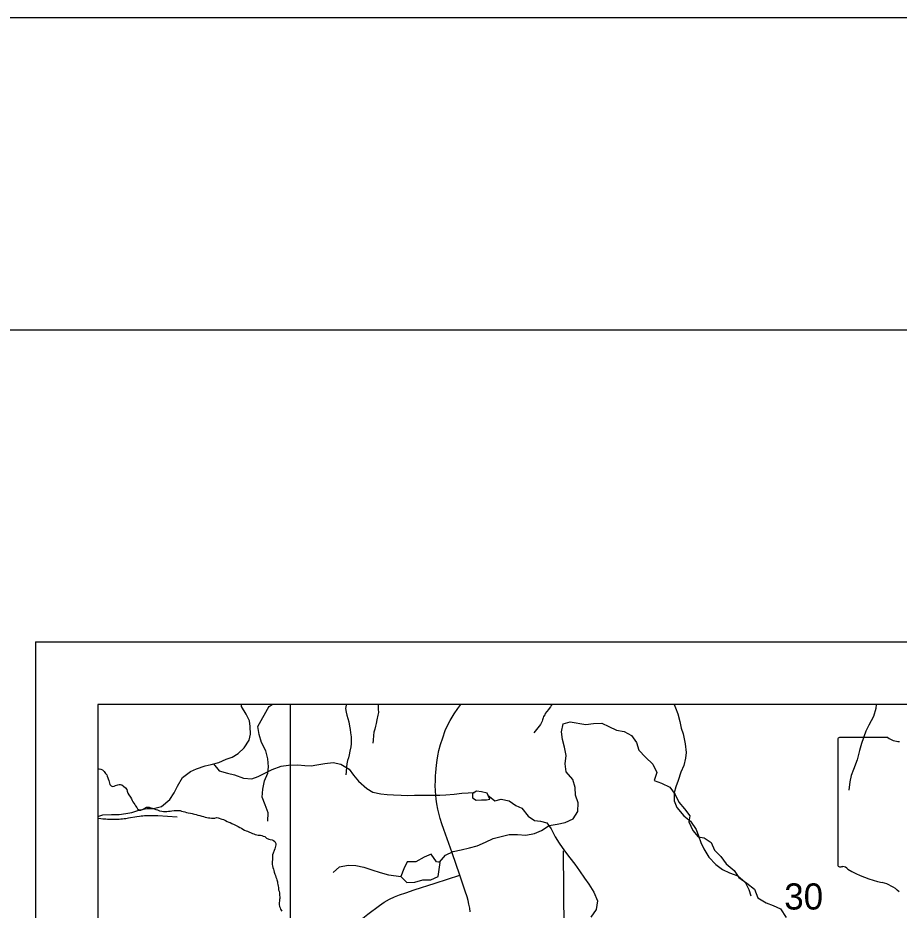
# Model space of a CAD drawing. Extents: x -21.1 to 50.3, y 0 to 22.1.
# Drawn here: x 1.972 to 3.383, y 20.57 to 22 of the extents above; entities that cross this region are included whole.
import ezdxf

# ---------------------------------------------------------------- set-up
doc = ezdxf.new("R2010")
doc.units = 0
for name, color, linetype in [('GM_X_County', 7, 'Continuous'), ('GM_X_County_Road', 7, 'Continuous'), ('GM_X_Minor_Lake', 7, 'Continuous'), ('GM_X_Minor_River', 7, 'Continuous'), ('GM_X_Section_Text', 7, 'Continuous'), ('GM_X_State_Route', 7, 'Continuous'), ('GM_X_State_Shield', 7, 'Continuous'), ('GM_X_Township_Road', 7, 'Continuous'), ('SH_Border', 7, 'Continuous'), ('SH_Cut_Line', 7, 'Continuous'), ('SH_Data', 7, 'Continuous')]:
    doc.layers.add(name, color=color, linetype=linetype)

msp = doc.modelspace()

# ---------------------------------------------------------------- linework, layer by layer
at = {"layer": 'GM_X_County'}
msp.add_lwpolyline([(8.9, 14.7464), (8.9, 20.9), (2.1, 20.9), (2.1, 14.1), (8.8932, 14.1)], dxfattribs=at)
at = {"layer": 'GM_X_County_Road'}
msp.add_lwpolyline([(2.4094, 20.2814), (2.4089, 20.3444), (2.4086, 20.5333), (2.4084, 20.714), (2.4086, 20.746), (2.4083, 20.9)], dxfattribs=at)
at = {"layer": 'GM_X_Minor_Lake'}
for points in [[(2.7234, 20.7578), (2.7144, 20.7601), (2.7064, 20.7608), (2.6999, 20.7574), (2.6999, 20.7502), (2.706, 20.7464), (2.7143, 20.7472), (2.7223, 20.7472), (2.7276, 20.7479)], [(2.7276, 20.7479), (2.7234, 20.7578)], [(2.648, 20.6469), (2.6422, 20.6475), (2.6338, 20.66), (2.6225, 20.6551), (2.6093, 20.6475), (2.5956, 20.6475), (2.59, 20.6365), (2.5854, 20.6244)], [(2.6473, 20.647), (2.6422, 20.6475), (2.6338, 20.66), (2.6225, 20.6551), (2.6093, 20.6475), (2.5956, 20.6475), (2.59, 20.6365), (2.5854, 20.6244)], [(2.5854, 20.6244), (2.5949, 20.6145), (2.6078, 20.6153), (2.6202, 20.6187), (2.6331, 20.6191), (2.6448, 20.6244), (2.648, 20.6469)], [(2.5854, 20.6244), (2.5949, 20.6145), (2.6078, 20.6153), (2.6202, 20.6187), (2.6331, 20.6191), (2.6448, 20.6244), (2.648, 20.6469)]]:
    msp.add_lwpolyline(points, dxfattribs=at)
at = {"layer": 'GM_X_Minor_River'}
msp.add_line((2.3741, 20.8968), (2.3791, 20.9), dxfattribs=at)
for points in [[(2.1669, 20.731), (2.1791, 20.7334), (2.189, 20.7331), (2.2018, 20.7365), (2.2151, 20.7478), (2.2219, 20.7585), (2.2273, 20.7691), (2.2356, 20.7827), (2.2481, 20.7926), (2.258, 20.7968), (2.272, 20.8013), (2.2815, 20.8036), (2.2936, 20.807), (2.3054, 20.812), (2.3148, 20.8154), (2.3247, 20.8214), (2.3342, 20.8302), (2.3425, 20.8427), (2.3444, 20.8525), (2.3441, 20.8643), (2.3426, 20.8738), (2.3376, 20.8844), (2.3301, 20.8965), (2.3301, 20.9)], [(2.3719, 20.7131), (2.3728, 20.7261), (2.3677, 20.7393), (2.3633, 20.7513), (2.3642, 20.7642), (2.3666, 20.7776), (2.3724, 20.7898), (2.373, 20.8001), (2.372, 20.813), (2.3688, 20.8258), (2.3618, 20.839), (2.3581, 20.8518), (2.3564, 20.8647), (2.3741, 20.8974)], [(2.4977, 20.9), (2.4974, 20.8989), (2.4966, 20.8936), (2.4974, 20.8875), (2.4986, 20.8826), (2.5002, 20.8773), (2.5021, 20.872), (2.503, 20.8651), (2.5038, 20.8595), (2.5046, 20.8545), (2.5054, 20.8481), (2.5058, 20.842), (2.5059, 20.8367), (2.5051, 20.8321), (2.5037, 20.8248), (2.5026, 20.8191), (2.5015, 20.8146), (2.5, 20.81), (2.4985, 20.805), (2.4982, 20.7997), (2.4975, 20.7921), (2.4972, 20.7871)], [(2.5485, 20.9), (2.5487, 20.8986), (2.5491, 20.8925), (2.5492, 20.8872), (2.5484, 20.8826), (2.547, 20.8754), (2.5459, 20.8696), (2.5448, 20.8651), (2.5433, 20.8605), (2.5418, 20.8555), (2.5415, 20.8502), (2.5408, 20.8426), (2.5404, 20.8377)], [(2.8273, 20.9), (2.8262, 20.8981), (2.8247, 20.8959), (2.8228, 20.8936), (2.8216, 20.8917), (2.8189, 20.8884), (2.8166, 20.8853), (2.8158, 20.8835), (2.8138, 20.8808), (2.813, 20.8785), (2.8122, 20.8751), (2.8114, 20.8732), (2.8099, 20.8698), (2.8087, 20.8676), (2.7981, 20.8545)], [(3.0232, 20.9), (3.0253, 20.8947), (3.029, 20.8849), (3.0321, 20.8727), (3.0343, 20.8621), (3.0377, 20.8526), (3.0408, 20.8367), (3.0423, 20.8231), (3.0411, 20.8136), (3.0385, 20.8022), (3.0339, 20.7912), (3.0294, 20.7783), (3.0256, 20.7681), (3.0229, 20.7582), (3.0233, 20.7453), (3.0271, 20.7347), (3.0384, 20.7214), (3.049, 20.7127), (3.0585, 20.6998), (3.0619, 20.6896), (3.0657, 20.6789), (3.0706, 20.6687), (3.0786, 20.6554), (3.0896, 20.6437), (3.1002, 20.6357), (3.1119, 20.63), (3.1248, 20.6255), (3.1366, 20.6152), (3.1426, 20.6035), (3.1456, 20.5932)], [(3.3466, 20.9), (3.3463, 20.8936), (3.3425, 20.8804), (3.3349, 20.8667), (3.33, 20.8572), (3.3232, 20.8375), (3.3201, 20.8261), (3.316, 20.8113), (3.3103, 20.7958), (3.3068, 20.7863), (3.3046, 20.7757), (3.303, 20.7628)], [(2.6473, 20.647), (2.657, 20.6582), (2.6693, 20.6641), (2.6818, 20.667), (2.6953, 20.6702), (2.7074, 20.6735), (2.7209, 20.679), (2.7329, 20.6849), (2.7457, 20.6882), (2.7589, 20.6915), (2.7721, 20.6913), (2.7854, 20.6904), (2.7993, 20.6929), (2.8106, 20.6981), (2.8226, 20.7059), (2.8354, 20.708), (2.8482, 20.7105), (2.861, 20.7164), (2.8687, 20.7283), (2.8692, 20.742), (2.8652, 20.7548), (2.8642, 20.7669), (2.8606, 20.7794), (2.8498, 20.7917), (2.8484, 20.805), (2.8501, 20.8179), (2.8472, 20.8315), (2.8444, 20.8436), (2.8426, 20.8561), (2.845, 20.8687), (2.8563, 20.8719), (2.8814, 20.8678), (2.8938, 20.8695), (2.9071, 20.8698), (2.9185, 20.8643), (2.9307, 20.8588), (2.9432, 20.8563), (2.9547, 20.8501), (2.9625, 20.8388), (2.9665, 20.8264), (2.9769, 20.8152), (2.9888, 20.804), (2.9955, 20.7908), (2.9908, 20.7782), (3.0029, 20.7739), (3.0159, 20.7673), (3.0248, 20.7557), (3.0303, 20.7433), (3.0396, 20.7328), (3.0481, 20.7212), (3.0464, 20.7117), (3.0527, 20.6977), (3.0616, 20.688), (3.0711, 20.6863), (3.0825, 20.6785), (3.0877, 20.6665), (3.0977, 20.6564), (3.1062, 20.6444), (3.1189, 20.6336), (3.1266, 20.6227), (3.1393, 20.6135), (3.1516, 20.6038)], [(2.2849, 20.8046), (2.2944, 20.7937), (2.3076, 20.7896), (2.319, 20.7873), (2.333, 20.7816), (2.3463, 20.7805), (2.3565, 20.7843), (2.3694, 20.7911), (2.3793, 20.7957), (2.3937, 20.801), (2.4051, 20.8025), (2.4202, 20.8029), (2.4312, 20.8021), (2.4414, 20.8017), (2.4509, 20.8029), (2.4634, 20.8055), (2.4767, 20.8067), (2.4892, 20.8044), (2.5025, 20.7961), (2.5093, 20.7866), (2.5176, 20.7771), (2.5309, 20.7653), (2.5404, 20.7593), (2.5529, 20.7566), (2.5631, 20.7555), (2.5737, 20.7551), (2.5855, 20.7543), (2.5957, 20.754), (2.6071, 20.7547), (2.6215, 20.7547), (2.6332, 20.7544), (2.6476, 20.7544), (2.6575, 20.7551), (2.6704, 20.7563), (2.6829, 20.7578), (2.703, 20.759)], [(2.1, 20.7974), (2.1015, 20.7969), (2.1046, 20.7961), (2.1072, 20.7949), (2.1098, 20.7922), (2.112, 20.7895), (2.1143, 20.7871), (2.115, 20.7848), (2.1175, 20.778), (2.1182, 20.7757), (2.1186, 20.7738), (2.1193, 20.7715), (2.1212, 20.7695), (2.1234, 20.7684)], [(2.1234, 20.7684), (2.1261, 20.7691), (2.128, 20.7698), (2.1319, 20.7712), (2.1338, 20.7716), (2.1364, 20.7719), (2.1383, 20.7711), (2.1409, 20.7692), (2.1439, 20.7661), (2.1462, 20.7634), (2.1469, 20.7607), (2.148, 20.758), (2.1494, 20.755), (2.152, 20.7515), (2.1539, 20.7488), (2.155, 20.7461), (2.1561, 20.7438), (2.1575, 20.7415), (2.159, 20.7396), (2.1601, 20.7377), (2.1623, 20.7346), (2.1634, 20.7327), (2.1665, 20.7307), (2.1687, 20.7303), (2.1714, 20.7318), (2.1749, 20.7336), (2.1779, 20.7351), (2.1802, 20.7354), (2.1821, 20.7354), (2.1848, 20.7342), (2.187, 20.7338), (2.1901, 20.7326), (2.1927, 20.7318), (2.1954, 20.7309), (2.1987, 20.7294), (2.2025, 20.7289), (2.2052, 20.7285), (2.2079, 20.7284), (2.2105, 20.7284), (2.2132, 20.7287), (2.2158, 20.729), (2.2185, 20.7294), (2.2219, 20.7301), (2.2242, 20.73), (2.2265, 20.73), (2.2284, 20.7299), (2.2315, 20.7299), (2.2337, 20.7291), (2.2364, 20.7283), (2.2394, 20.7278), (2.242, 20.727), (2.2447, 20.7262), (2.2481, 20.7258), (2.2508, 20.7254), (2.2526, 20.7246), (2.2549, 20.7241), (2.2572, 20.7233), (2.2598, 20.7225), (2.2632, 20.7217), (2.2663, 20.7209), (2.2689, 20.7201), (2.2719, 20.7193), (2.2746, 20.7188), (2.2772, 20.7184), (2.2795, 20.718), (2.2818, 20.7176), (2.2848, 20.7179), (2.2871, 20.7178), (2.2898, 20.7186), (2.2924, 20.7181), (2.2985, 20.7161), (2.3011, 20.7153), (2.3042, 20.7141), (2.3068, 20.7125), (2.3098, 20.7113), (2.3117, 20.7105), (2.3143, 20.709), (2.3181, 20.7078), (2.3204, 20.7066), (2.3226, 20.7054), (2.3249, 20.7042), (2.3275, 20.703), (2.3298, 20.7019), (2.332, 20.7003), (2.3347, 20.6987), (2.3373, 20.6975), (2.3396, 20.6967), (2.3418, 20.6956), (2.3452, 20.694), (2.3475, 20.6932), (2.3498, 20.6927), (2.352, 20.6916), (2.3543, 20.6911), (2.3566, 20.6907), (2.3585, 20.6903), (2.3604, 20.6903), (2.3626, 20.6899), (2.3645, 20.6891), (2.3672, 20.6882), (2.3698, 20.6859), (2.3736, 20.6843)], [(2.7247, 20.7548), (2.736, 20.7456), (2.7458, 20.7479), (2.7587, 20.7456), (2.7693, 20.7381), (2.7792, 20.7339), (2.7894, 20.721), (2.7992, 20.7138), (2.8091, 20.7127), (2.8189, 20.7104), (2.8258, 20.7005), (2.8326, 20.6876), (2.839, 20.6778), (2.8474, 20.6656), (2.8557, 20.6543), (2.864, 20.644), (2.8712, 20.6334), (2.8795, 20.6216), (2.8864, 20.6118), (2.8943, 20.5989), (2.9, 20.5852), (2.8981, 20.5716), (2.8898, 20.5591)], [(2.1, 20.7206), (2.1077, 20.723), (2.1217, 20.7234), (2.1342, 20.7237), (2.1445, 20.7253), (2.1543, 20.7268), (2.1669, 20.731)], [(2.3736, 20.6843), (2.3758, 20.6835), (2.3789, 20.6831), (2.3815, 20.6819), (2.3834, 20.6804), (2.3852, 20.6769), (2.3852, 20.675), (2.3847, 20.6727), (2.3839, 20.6705), (2.3835, 20.6686), (2.3823, 20.6659), (2.3807, 20.6614), (2.3799, 20.6591), (2.3795, 20.655), (2.3794, 20.6516), (2.379, 20.6478), (2.3789, 20.6455), (2.3793, 20.6432), (2.3796, 20.6413), (2.3803, 20.6386), (2.381, 20.636), (2.3817, 20.6337), (2.3825, 20.6314), (2.3835, 20.6279), (2.3842, 20.6256), (2.385, 20.623), (2.3861, 20.6211), (2.3868, 20.6191), (2.3875, 20.6157), (2.3878, 20.6138), (2.3882, 20.6115), (2.3889, 20.6088), (2.3892, 20.6066), (2.3895, 20.6031), (2.3902, 20.6008), (2.3909, 20.5974), (2.3909, 20.5944), (2.3912, 20.5913), (2.3912, 20.5891), (2.3908, 20.5872), (2.3907, 20.5853), (2.3903, 20.5819), (2.3902, 20.5796), (2.3909, 20.5761), (2.3917, 20.5742), (2.3924, 20.5719), (2.3946, 20.5689)], [(2.477, 20.6304), (2.4871, 20.6396), (2.5006, 20.6425), (2.5131, 20.6416), (2.5257, 20.6392), (2.539, 20.6349), (2.5519, 20.6305), (2.5656, 20.627), (2.5856, 20.6244)], [(3.1516, 20.6038), (3.157, 20.5901), (3.1703, 20.5821), (3.1817, 20.5776), (3.1935, 20.5722), (3.2023, 20.5586)]]:
    msp.add_lwpolyline(points, dxfattribs=at)
at = {"layer": 'GM_X_State_Route'}
msp.add_lwpolyline([(6.5295, 20.9), (2.1, 20.9), (2.1, 17.7402), (2.4285, 17.7463), (2.7321, 17.7529), (3.033, 17.7583), (3.3026, 17.7626), (3.4415, 17.7683), (3.9402, 17.7717), (5.3307, 17.7918), (6.522, 17.8104), (6.5223, 18.3569), (6.5225, 18.9778), (6.5227, 19.3467), (6.5298, 20.3986)], close=True, dxfattribs=at)
at = {"layer": 'GM_X_State_Shield'}
for p, q in [((3.3651, 20.8468), (3.2879, 20.8468)), ((3.2853, 20.8434), (3.2853, 20.6433))]:
    msp.add_line(p, q, dxfattribs=at)
for centre, radius, start, end in [((3.2883, 20.8438), 0.00305, 98.1301, 188.1301), ((3.3835, 20.8701), 0.0296, 231.6195, 271.1119), ((3.2884, 20.6428), 0.00308, 171.9584, 258.3066), ((3.2888, 20.6633), 0.0235, 267.339, 280.6039), ((3.2936, 20.6317), 0.00848, 29.7484, 93.2717), ((3.4007, 20.8115), 0.2019, 240.4129, 257.1985), ((3.3405, 20.5534), 0.0632, 47.1842, 75.836)]:
    msp.add_arc(centre, radius, start, end, dxfattribs=at)
at = {"layer": 'GM_X_Township_Road'}
for points in [[(2.6962, 20.5678), (2.6955, 20.5736), (2.6942, 20.5799), (2.6928, 20.586), (2.6913, 20.5915), (2.6882, 20.6009), (2.6797, 20.6263), (2.6673, 20.6622), (2.6543, 20.6996), (2.6511, 20.7087), (2.6484, 20.7174), (2.6466, 20.7238), (2.6446, 20.7322), (2.6429, 20.7406), (2.6418, 20.748), (2.6411, 20.7546), (2.6407, 20.761), (2.6404, 20.7708), (2.6405, 20.7768), (2.6409, 20.7855), (2.6412, 20.7908), (2.6418, 20.7967), (2.6425, 20.8027), (2.6436, 20.8107), (2.6445, 20.8173), (2.6462, 20.8261), (2.6488, 20.8358), (2.6523, 20.8463), (2.6564, 20.8582), (2.6605, 20.8673), (2.6641, 20.8744), (2.6708, 20.8848), (2.6767, 20.8935), (2.6815, 20.9)], [(2.1, 20.7178), (2.1049, 20.7172), (2.1076, 20.7168), (2.1102, 20.7166), (2.1128, 20.7164), (2.1155, 20.7162), (2.1181, 20.7161), (2.1208, 20.716), (2.1314, 20.7161), (2.1341, 20.7163), (2.1367, 20.7165), (2.1393, 20.7167), (2.142, 20.717), (2.1446, 20.7173), (2.1489, 20.718), (2.1621, 20.7201), (2.1668, 20.7208), (2.1695, 20.7212), (2.1721, 20.7214), (2.1748, 20.7217), (2.1774, 20.7219), (2.1801, 20.722), (2.1827, 20.7221), (2.1933, 20.722), (2.196, 20.7219), (2.2271, 20.72)], [(2.8469, 20.539), (2.8457, 20.6655)], [(2.4086, 20.5333), (2.4294, 20.5332), (2.4532, 20.533), (2.4614, 20.5333), (2.4665, 20.5336), (2.4733, 20.5343), (2.4798, 20.5351), (2.4865, 20.5368), (2.4917, 20.5386), (2.4964, 20.5406), (2.5021, 20.5433), (2.5086, 20.5468), (2.5153, 20.5509), (2.5242, 20.5573), (2.5326, 20.5637), (2.5512, 20.5778), (2.5586, 20.5829), (2.5669, 20.5877), (2.5748, 20.5915), (2.5831, 20.5948), (2.5932, 20.5983), (2.6067, 20.6029), (2.6404, 20.6137), (2.6797, 20.6263)]]:
    msp.add_lwpolyline(points, dxfattribs=at)
at = {"layer": 'SH_Border'}
msp.add_lwpolyline([(1.5, 21.5), (33.5, 21.5), (33.5, 0.5), (1.5, 0.5)], close=True, dxfattribs=at)
at = {"layer": 'SH_Cut_Line'}
for points in [[(0, 0), (34, 0), (34, 22), (0, 22)], [(6.5295, 20.9), (2.1, 20.9), (2.1, 14.1), (6.5099, 14.1), (6.5113, 14.2435), (6.5111, 14.2942), (6.513, 14.4147), (6.5128, 14.6032), (6.5142, 14.9441), (6.5146, 15.0349), (6.514, 15.0936), (6.5146, 15.3031), (6.5159, 15.4923), (6.5198, 16.0826), (6.5212, 16.2452), (6.5232, 16.4681), (6.5222, 16.8567), (6.5201, 17.6965), (6.5205, 17.7208), (6.522, 17.8104), (6.5223, 18.3569), (6.5225, 18.9778), (6.5227, 19.3467), (6.5298, 20.3986)]]:
    msp.add_lwpolyline(points, close=True, dxfattribs=at)
at = {"layer": 'SH_Data'}
for q in [(9, 21), (2, 14)]:
    msp.add_line((2, 21), q, dxfattribs=at)

# ---------------------------------------------------------------- texts
at = {"layer": 'GM_X_Section_Text'}
msp.add_text('30', height=0.04186, rotation=0, dxfattribs=at).set_placement((3.1994, 20.5713))

doc.saveas('drawing.dxf')
